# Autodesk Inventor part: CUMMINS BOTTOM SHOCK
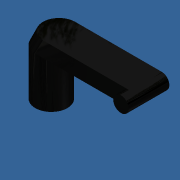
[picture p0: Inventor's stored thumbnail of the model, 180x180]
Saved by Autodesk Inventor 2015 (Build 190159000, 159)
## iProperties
Created: 2014-10
Part Number: CUMMINS BOTTOM SHOCK
Material: Generic
Document SubType Name: Modeling
Designer: caovt
Density: 1 g/cm^3
Appearance: Default
Author: caovt
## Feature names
1. Extrusion1
2. Extrusion2
3. Sweep1
4. Extrusion6
5. Extrusion7
## Parameters: d0 = 4.572 mm, d1 = 27.94 mm, d2 = 20.35054 mm, d3 = 25.65051 mm, d4 = 9.525 mm, d5 = 0, d6 = 9.525 mm, d7 = 13.97 mm, d8 = 0, d9 = 0, d10 = 0, d24 = 4.572 mm, d25 = 2.54 mm, d26 = 39.6875 mm, d27 = 0, d28 = 0, d29 = 25.4 mm, d30 = 0
